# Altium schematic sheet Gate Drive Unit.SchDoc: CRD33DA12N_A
size 431 x 279 mm; Date: 09.11.2024; Revision: 2; SheetNumber: 2; SheetTotal: 3; SheetSize: B
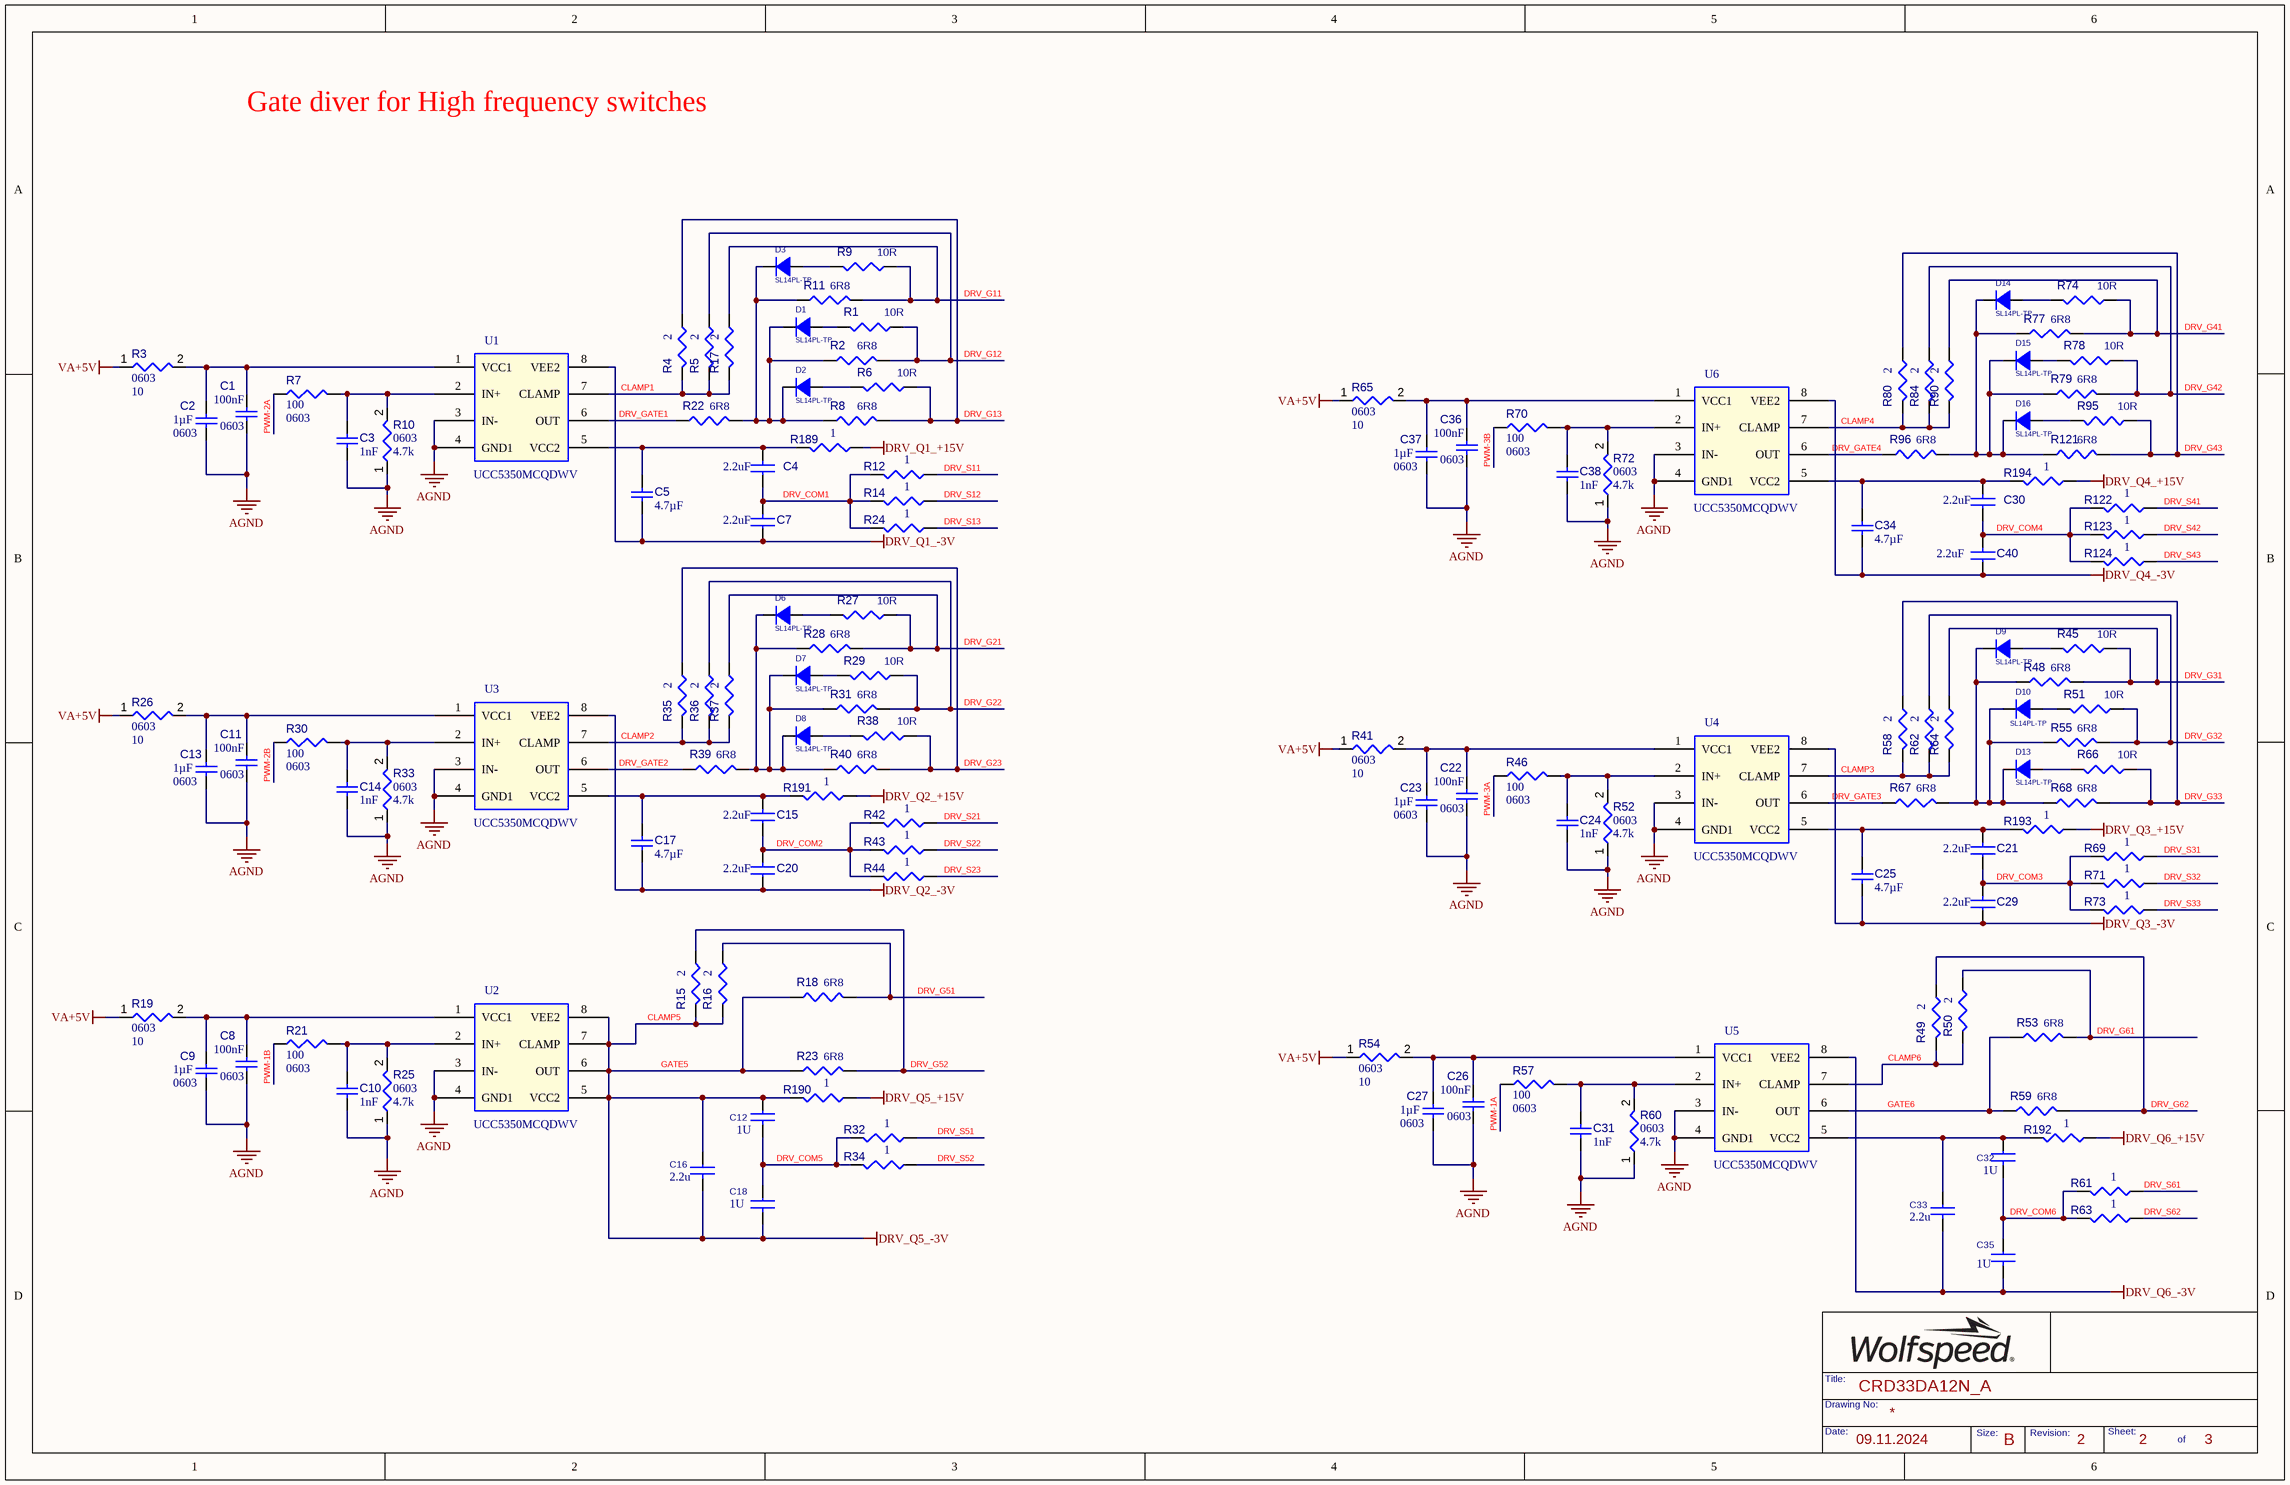
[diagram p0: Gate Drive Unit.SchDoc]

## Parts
C1  value 100nF  Case/Package: 0603  [FP-C0603C-CF-IPC_B]  (hidden comment: C0603C104K5RAC7411)
C2  value 1µF  Case/Package: 0603  [FP-C0603C-CF-IPC_B]  (hidden comment: C1608X7R1V105K080AE)
C3  value 1nF  [FP-C0603C-CF-IPC_B]  (hidden comment: GRM1885C1H102GA01D)
C4  value 2.2uF  [C0603]  (hidden comment: C1608X7R1V225K080AE)
C5  value 4.7µF  [CAPC2012X15N]  (hidden comment: C2012X7R1H475K125AC)
C7  value 2.2uF  [C0603]  (hidden comment: C1608X7R1V225K080AE)
C8  value 100nF  Case/Package: 0603  [FP-C0603C-CF-IPC_B]  (hidden comment: C0603C104K5RAC7411)
C9  value 1µF  Case/Package: 0603  [FP-C0603C-CF-IPC_B]  (hidden comment: C1608X7R1V105K080AE)
C10  value 1nF  [FP-C0603C-CF-IPC_B]  (hidden comment: GRM1885C1H102GA01D)
C11  value 100nF  Case/Package: 0603  [FP-C0603C-CF-IPC_B]  (hidden comment: C0603C104K5RAC7411)
C12  1U  [C0603]
C13  value 1µF  Case/Package: 0603  [FP-C0603C-CF-IPC_B]  (hidden comment: C1608X7R1V105K080AE)
C14  value 1nF  [FP-C0603C-CF-IPC_B]  (hidden comment: GRM1885C1H102GA01D)
C15  value 2.2uF  [C0603]  (hidden comment: C1608X7R1V225K080AE)
C16  2.2u  [C0805]
C17  value 4.7µF  [CAPC2012X15N]  (hidden comment: C2012X7R1H475K125AC)
C18  1U  [C0603]
C20  value 2.2uF  [C0603]  (hidden comment: C1608X7R1V225K080AE)
C21  value 2.2uF  [C0603]  (hidden comment: C1608X7R1V225K080AE)
C22  value 100nF  Case/Package: 0603  [FP-C0603C-CF-IPC_B]  (hidden comment: C0603C104K5RAC7411)
C23  value 1µF  Case/Package: 0603  [FP-C0603C-CF-IPC_B]  (hidden comment: C1608X7R1V105K080AE)
C24  value 1nF  [FP-C0603C-CF-IPC_B]  (hidden comment: GRM1885C1H102GA01D)
C25  value 4.7µF  [CAPC2012X15N]  (hidden comment: C2012X7R1H475K125AC)
C26  value 100nF  Case/Package: 0603  [FP-C0603C-CF-IPC_B]  (hidden comment: C0603C104K5RAC7411)
C27  value 1µF  Case/Package: 0603  [FP-C0603C-CF-IPC_B]  (hidden comment: C1608X7R1V105K080AE)
C29  value 2.2uF  [C0603]  (hidden comment: C1608X7R1V225K080AE)
C30  value 2.2uF  [C0603]  (hidden comment: C1608X7R1V225K080AE)
C31  value 1nF  [FP-C0603C-CF-IPC_B]  (hidden comment: GRM1885C1H102GA01D)
C32  1U  [C0603]
C33  2.2u  [C0805]
C34  value 4.7µF  [CAPC2012X15N]  (hidden comment: C2012X7R1H475K125AC)
C35  1U  [C0603]
C36  value 100nF  Case/Package: 0603  [FP-C0603C-CF-IPC_B]  (hidden comment: C0603C104K5RAC7411)
C37  value 1µF  Case/Package: 0603  [FP-C0603C-CF-IPC_B]  (hidden comment: C1608X7R1V105K080AE)
C38  value 1nF  [FP-C0603C-CF-IPC_B]  (hidden comment: GRM1885C1H102GA01D)
C40  value 2.2uF  [C0603]  (hidden comment: C1608X7R1V225K080AE)
D1  SL14PL-TP  [SMDSOD123]
D2  SL14PL-TP  [SMDSOD123]
D3  SL14PL-TP  [SMDSOD123]
D6  SL14PL-TP  [SMDSOD123]
D7  SL14PL-TP  [SMDSOD123]
D8  SL14PL-TP  [SMDSOD123]
D9  SL14PL-TP  [SMDSOD123]
D10  SL14PL-TP  [SMDSOD123]
D13  SL14PL-TP  [SMDSOD123]
D14  SL14PL-TP  [SMDSOD123]
D15  SL14PL-TP  [SMDSOD123]
D16  SL14PL-TP  [SMDSOD123]
R1  10R  [R1206]
R2  6R8  [R1206]
R3  value 10  Case/Package: 0603  [FP-AC0603-IPC_B]  (hidden comment: AC0603FR-0710RL)
R4  value 2  [RESC3015X06N]  (hidden comment: RMCF1206FT2R00)
R5  value 2  [RESC3015X06N]  (hidden comment: RMCF1206FT2R00)
R6  10R  [R1206]
R7  value 100  Case/Package: 0603  [FP-AC0603-IPC_B]  (hidden comment: RMCF0603FT100R)
R8  6R8  [R1206]
R9  10R  [R1206]
R10  value 4.7k  Case/Package: 0603  [FP-AC0603-IPC_B]  (hidden comment: RMCF0603FT4K70)
R11  6R8  [R1206]
R12  value 1  [RESC3015X06N]  (hidden comment: RMCF1206FT1R00)
R14  value 1  [RESC3015X06N]  (hidden comment: RMCF1206FT1R00)
R15  value 2  [RESC3015X06N]  (hidden comment: RMCF1206FT2R00)
R16  value 2  [RESC3015X06N]  (hidden comment: RMCF1206FT2R00)
R17  value 2  [RESC3015X06N]  (hidden comment: RMCF1206FT2R00)
R18  6R8  [R1206]
R19  value 10  Case/Package: 0603  [FP-AC0603-IPC_B]  (hidden comment: AC0603FR-0710RL)
R21  value 100  Case/Package: 0603  [FP-AC0603-IPC_B]  (hidden comment: RMCF0603FT100R)
R22  6R8  [R1206]
R23  6R8  [R1206]
R24  value 1  [RESC3015X06N]  (hidden comment: RMCF1206FT1R00)
R25  value 4.7k  Case/Package: 0603  [FP-AC0603-IPC_B]  (hidden comment: RMCF0603FT4K70)
R26  value 10  Case/Package: 0603  [FP-AC0603-IPC_B]  (hidden comment: AC0603FR-0710RL)
R27  10R  [R1206]
R28  6R8  [R1206]
R29  10R  [R1206]
R30  value 100  Case/Package: 0603  [FP-AC0603-IPC_B]  (hidden comment: RMCF0603FT100R)
R31  6R8  [R1206]
R32  value 1  [RESC3015X06N]  (hidden comment: RMCF1206FT1R00)
R33  value 4.7k  Case/Package: 0603  [FP-AC0603-IPC_B]  (hidden comment: RMCF0603FT4K70)
R34  value 1  [RESC3015X06N]  (hidden comment: RMCF1206FT1R00)
R35  value 2  [RESC3015X06N]  (hidden comment: RMCF1206FT2R00)
R36  value 2  [RESC3015X06N]  (hidden comment: RMCF1206FT2R00)
R37  value 2  [RESC3015X06N]  (hidden comment: RMCF1206FT2R00)
R38  10R  [R1206]
R39  6R8  [R1206]
R40  6R8  [R1206]
R41  value 10  Case/Package: 0603  [FP-AC0603-IPC_B]  (hidden comment: AC0603FR-0710RL)
R42  value 1  [RESC3015X06N]  (hidden comment: RMCF1206FT1R00)
R43  value 1  [RESC3015X06N]  (hidden comment: RMCF1206FT1R00)
R44  value 1  [RESC3015X06N]  (hidden comment: RMCF1206FT1R00)
R45  10R  [R1206]
R46  value 100  Case/Package: 0603  [FP-AC0603-IPC_B]  (hidden comment: RMCF0603FT100R)
R48  6R8  [R1206]
R49  value 2  [RESC3015X06N]  (hidden comment: RMCF1206FT2R00)
R50  value 2  [RESC3015X06N]  (hidden comment: RMCF1206FT2R00)
R51  10R  [R1206]
R52  value 4.7k  Case/Package: 0603  [FP-AC0603-IPC_B]  (hidden comment: RMCF0603FT4K70)
R53  6R8  [R1206]
R54  value 10  Case/Package: 0603  [FP-AC0603-IPC_B]  (hidden comment: AC0603FR-0710RL)
R55  6R8  [R1206]
R57  value 100  Case/Package: 0603  [FP-AC0603-IPC_B]  (hidden comment: RMCF0603FT100R)
R58  value 2  [RESC3015X06N]  (hidden comment: RMCF1206FT2R00)
R59  6R8  [R1206]
R60  value 4.7k  Case/Package: 0603  [FP-AC0603-IPC_B]  (hidden comment: RMCF0603FT4K70)
R61  value 1  [RESC3015X06N]  (hidden comment: RMCF1206FT1R00)
R62  value 2  [RESC3015X06N]  (hidden comment: RMCF1206FT2R00)
R63  value 1  [RESC3015X06N]  (hidden comment: RMCF1206FT1R00)
R64  value 2  [RESC3015X06N]  (hidden comment: RMCF1206FT2R00)
R65  value 10  Case/Package: 0603  [FP-AC0603-IPC_B]  (hidden comment: AC0603FR-0710RL)
R66  10R  [R1206]
R67  6R8  [R1206]
R68  6R8  [R1206]
R69  value 1  [RESC3015X06N]  (hidden comment: RMCF1206FT1R00)
R70  value 100  Case/Package: 0603  [FP-AC0603-IPC_B]  (hidden comment: RMCF0603FT100R)
R71  value 1  [RESC3015X06N]  (hidden comment: RMCF1206FT1R00)
R72  value 4.7k  Case/Package: 0603  [FP-AC0603-IPC_B]  (hidden comment: RMCF0603FT4K70)
R73  value 1  [RESC3015X06N]  (hidden comment: RMCF1206FT1R00)
R74  10R  [R1206]
R77  6R8  [R1206]
R78  10R  [R1206]
R79  6R8  [R1206]
R80  value 2  [RESC3015X06N]  (hidden comment: RMCF1206FT2R00)
R84  value 2  [RESC3015X06N]  (hidden comment: RMCF1206FT2R00)
R90  value 2  [RESC3015X06N]  (hidden comment: RMCF1206FT2R00)
R95  10R  [R1206]
R96  6R8  [R1206]
R121  6R8  [R1206]
R122  value 1  [RESC3015X06N]  (hidden comment: RMCF1206FT1R00)
R123  value 1  [RESC3015X06N]  (hidden comment: RMCF1206FT1R00)
R124  value 1  [RESC3015X06N]  (hidden comment: RMCF1206FT1R00)
R189  value 1  [RESC3015X06N]  (hidden comment: RMCF1206FT1R00)
R190  value 1  [RESC3015X06N]  (hidden comment: RMCF1206FT1R00)
R191  value 1  [RESC3015X06N]  (hidden comment: RMCF1206FT1R00)
R192  value 1  [RESC3015X06N]  (hidden comment: RMCF1206FT1R00)
R193  value 1  [RESC3015X06N]  (hidden comment: RMCF1206FT1R00)
R194  value 1  [RESC3015X06N]  (hidden comment: RMCF1206FT1R00)
U1  UCC5350MCQDWV  [SOIC8_DWV]
U2  UCC5350MCQDWV  [SOIC8_DWV]
U3  UCC5350MCQDWV  [SOIC8_DWV]
U4  UCC5350MCQDWV  [SOIC8_DWV]
U5  UCC5350MCQDWV  [SOIC8_DWV]
U6  UCC5350MCQDWV  [SOIC8_DWV]

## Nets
AGND: C1.1 C2.2 C3.1 C8.1 C9.2 C10.1 C11.1 C13.2 C14.1 C22.1 C23.2 C24.1 C26.1 C27.2 C31.1 C36.1 C37.2 C38.1 R10.1 R25.1 R33.1 R52.1 R60.1 R72.1 U1.3(IN-) U1.4(GND1) U2.3(IN-) U2.4(GND1) U3.3(IN-) U3.4(GND1) U4.3(IN-) U4.4(GND1) U5.3(IN-) U5.4(GND1) U6.3(IN-) U6.4(GND1)
CLAMP5: C12.1 C16.1 C16.2 C18.2 R15.2 R16.2 R18.1 R23.1 R190.2 U2.5(VCC2) U2.6(OUT) U2.7(CLAMP) U2.8(VEE2)  [also labelled DRV_Q5_-3V, GATE5]
DRV_Q1_+15V: R189.1
DRV_Q1_-3V: C5.1 C7.1 U1.8(VEE2)
DRV_Q2_+15V: R191.1
DRV_Q2_-3V: C17.1 C20.1 U3.8(VEE2)
DRV_Q3_+15V: R193.1
DRV_Q3_-3V: C25.1 C29.1 U4.8(VEE2)
DRV_Q4_+15V: R194.1
DRV_Q4_-3V: C34.1 C40.1 U6.8(VEE2)
DRV_Q5_+15V: R190.1
DRV_Q6_+15V: R192.1
DRV_Q6_-3V: C33.2 C35.2 U5.8(VEE2)
VA+5V: R3.1 R19.1 R26.1 R41.1 R54.1 R65.1
CLAMP1: R4.2 R5.2 R17.2 U1.7(CLAMP)
CLAMP2: R35.2 R36.2 R37.2 U3.7(CLAMP)
CLAMP3: R58.2 R62.2 R64.2 U4.7(CLAMP)
CLAMP4: R80.2 R84.2 R90.2 U6.7(CLAMP)
CLAMP6: R49.2 R50.2 U5.7(CLAMP)
DRV_COM1: C4.1 C7.2 R12.2 R14.2 R24.2
DRV_COM2: C15.1 C20.2 R42.2 R43.2 R44.2
DRV_COM3: C21.1 C29.2 R69.2 R71.2 R73.2
DRV_COM4: C30.1 C40.2 R122.2 R123.2 R124.2
DRV_COM5: C12.2 C18.1 R32.2 R34.2
DRV_COM6: C32.2 C35.1 R61.2 R63.2
DRV_G11: R9.1 R11.2 R17.1
DRV_G12: R1.1 R2.2 R5.1
DRV_G13: R4.1 R6.1 R8.2
DRV_G21: R27.1 R28.2 R37.1
DRV_G22: R29.1 R31.2 R36.1
DRV_G23: R35.1 R38.1 R40.2
DRV_G31: R45.1 R48.2 R64.1
DRV_G32: R51.1 R55.2 R62.1
DRV_G33: R58.1 R66.1 R68.2
DRV_G41: R74.1 R77.2 R90.1
DRV_G42: R78.1 R79.2 R84.1
DRV_G43: R80.1 R95.1 R121.2
DRV_G51: R16.1 R18.2
DRV_G52: R15.1 R23.2
DRV_G61: R50.1 R53.2
DRV_G62: R49.1 R59.2
DRV_GATE1: R22.1 U1.6(OUT)
DRV_GATE2: R39.1 U3.6(OUT)
DRV_GATE3: R67.1 U4.6(OUT)
DRV_GATE4: R96.1 U6.6(OUT)
DRV_S11: R12.1
DRV_S12: R14.1
DRV_S13: R24.1
DRV_S21: R42.1
DRV_S22: R43.1
DRV_S23: R44.1
DRV_S31: R69.1
DRV_S32: R71.1
DRV_S33: R73.1
DRV_S41: R122.1
DRV_S42: R123.1
DRV_S43: R124.1
DRV_S51: R32.1
DRV_S52: R34.1
DRV_S61: R61.1
DRV_S62: R63.1
GATE6: R53.1 R59.1 U5.6(OUT)
PWM-1A: R57.1
PWM-1B: R21.1
PWM-2A: R7.1
PWM-2B: R30.1
PWM-3A: R46.1
PWM-3B: R70.1
NetC1_2: C1.2 C2.1 R3.2 U1.1(VCC1)
NetC3_2: C3.2 R7.2 R10.2 U1.2(IN+)
NetC4_2: C4.2 C5.2 R189.2 U1.5(VCC2)
NetC8_2: C8.2 C9.1 R19.2 U2.1(VCC1)
NetC10_2: C10.2 R21.2 R25.2 U2.2(IN+)
NetC11_2: C11.2 C13.1 R26.2 U3.1(VCC1)
NetC14_2: C14.2 R30.2 R33.2 U3.2(IN+)
NetC15_2: C15.2 C17.2 R191.2 U3.5(VCC2)
NetC21_2: C21.2 C25.2 R193.2 U4.5(VCC2)
NetC22_2: C22.2 C23.1 R41.2 U4.1(VCC1)
NetC24_2: C24.2 R46.2 R52.2 U4.2(IN+)
NetC26_2: C26.2 C27.1 R54.2 U5.1(VCC1)
NetC30_2: C30.2 C34.2 R194.2 U6.5(VCC2)
NetC31_2: C31.2 R57.2 R60.2 U5.2(IN+)
NetC32_1: C32.1 C33.1 R192.2 U5.5(VCC2)
NetC36_2: C36.2 C37.1 R65.2 U6.1(VCC1)
NetC38_2: C38.2 R70.2 R72.2 U6.2(IN+)
NetD1_1: D1.1(A) R1.2
NetD1_2: D1.2(K) D2.2(K) D3.2(K) R2.1 R8.1 R11.1 R22.2
NetD2_1: D2.1(A) R6.2
NetD3_1: D3.1(A) R9.2
NetD6_1: D6.1(A) R27.2
NetD6_2: D6.2(K) D7.2(K) D8.2(K) R28.1 R31.1 R39.2 R40.1
NetD7_1: D7.1(A) R29.2
NetD8_1: D8.1(A) R38.2
NetD9_1: D9.1(A) R45.2
NetD9_2: D9.2(K) D10.2(K) D13.2(K) R48.1 R55.1 R67.2 R68.1
NetD10_1: D10.1(A) R51.2
NetD13_1: D13.1(A) R66.2
NetD14_1: D14.1(A) R74.2
NetD14_2: D14.2(K) D15.2(K) D16.2(K) R77.1 R79.1 R96.2 R121.1
NetD15_1: D15.1(A) R78.2
NetD16_1: D16.1(A) R95.2

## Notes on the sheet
- Gate diver for High frequency switches

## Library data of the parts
C1 C8 C11 C22 C26 C36 = CMP-001-00086-7: Ceramic Capacitor, Multilayer, Ceramic, 50V, 10% +Tol, 10% -Tol, X7R, 15% TC, 0.1uF, Surface Mount, 0603
C2 C9 C13 C23 C27 C37 = CMP-001-00097-9: Ceramic Capacitor, Multilayer, Ceramic, 35V, 10% +Tol, 10% -Tol, X7R, 15% TC, 1uF, Surface Mount, 0603
C3 C10 C14 C24 C31 C38 = CMP-001-00098-7: Ceramic Capacitor, Multilayer, Ceramic, 50V, 2% +Tol, 2% -Tol, C0G, -/+30ppm/Cel TC, 0.001uF, Surface Mount, 0603
C4 C7 C15 C20 C21 C29 C30 C40 = CAP NP_Dup1_3
C5 C17 C25 C34 = CMP-001-00093-6: Ceramic Capacitor, Multilayer, Ceramic, 50V, 10% +Tol, 10% -Tol, X7R, 15% TC, 4.7uF, Surface Mount, 0805
C12 C18 C32 C35 = CAP NP
C16 C33 = CAP NP: C2012X7R1H225K125AC
D1-D3 D6-D10 D13-D16 = DIODE_0: DIODE SCHOTTKY 40V 1A SOD123FL; Manufacturer: Micro Commercia; PCB Footprint: SOD-123
R1 R2 R6 R8 R9 R11 R18 R22 R23 R27-R29 R31 R38-R40 R45 R48 R51 R53 R55 R59 R66-R68 R74 R77-R79 R95 R96 R121 = R
R3 R19 R26 R41 R54 R65 = CMP-009-00002-2: Fixed Resistor, Metal Glaze/thick Film, 0.1W, 10ohm, 75V, 1% +/-Tol, 200ppm/Cel, Surface Mount, 0603; Power: 100mW
R4 R5 R15-R17 R35-R37 R49 R50 R58 R62 R64 R80 R84 R90 = CMP-009-00060-6: Fixed Resistor, Metal Glaze/thick Film, 0.25W, 2ohm, 200V, 1% +/-Tol, 200ppm/Cel, Surface Mount, 1206; Power: 250mW
R7 R21 R30 R46 R57 R70 = CMP-009-00005-3: Fixed Resistor, Metal Glaze/thick Film, 0.1W, 100ohm, 75V, 1% +/-Tol, 100ppm/Cel, Surface Mount, 0603; Power: 100mW
R10 R25 R33 R52 R60 R72 = CMP-009-00035-2: Fixed Resistor, Metal Glaze/thick Film, 0.1W, 4700ohm, 75V, 1% +/-Tol, 100ppm/Cel, Surface Mount, 0603; Power: 100mW
R12 R14 R24 R32 R34 R42-R44 R61 R63 R69 R71 R73 R122-R124 R189-R194 = CMP-009-00086-4: Fixed Resistor, Metal Glaze/thick Film, 0.25W, 1ohm, 200V, 1% +/-Tol, 200ppm/Cel, Surface Mount, 1206; Power: 250mW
